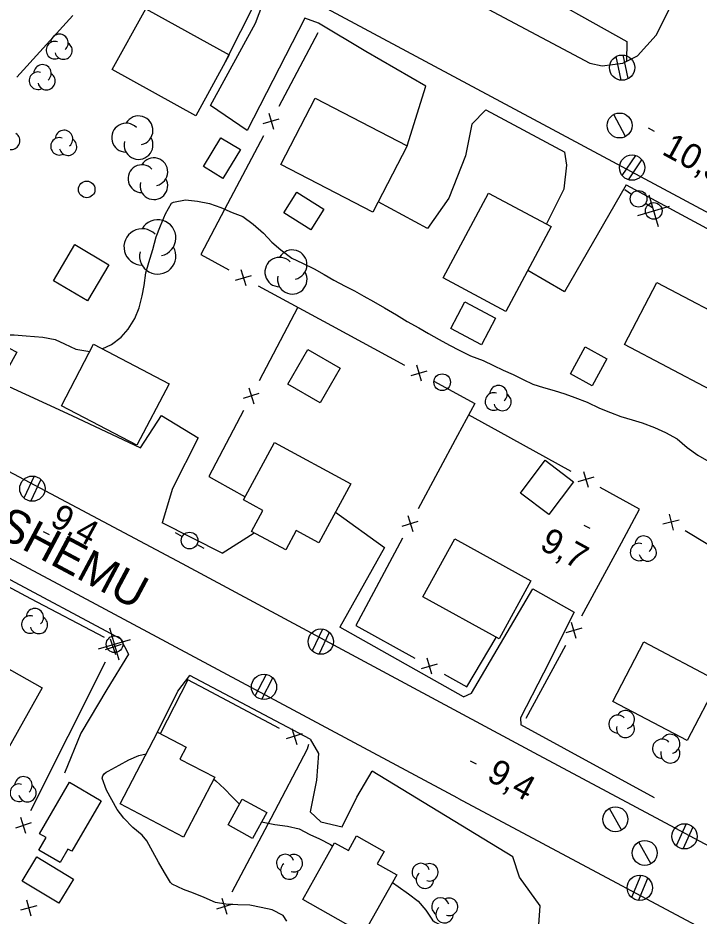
# Model space of a CAD drawing. Extents: x 219136 to 222520, y 5421589 to 5424530.
# Drawn here: x 220838.9 to 220920.8, y 5423443.6 to 5423551.5 of the extents above; entities that cross this region are included whole.
import ezdxf

# ---------------------------------------------------------------- set-up
doc = ezdxf.new("R2010")
doc.units = 0
for name, color, linetype in [('Level 1', 7, 'Continuous'), ('Level 19', 7, 'Continuous'), ('Level 21', 7, 'Continuous'), ('Level 3', 7, 'Continuous'), ('Level 31', 7, 'Continuous'), ('Level 36', 7, 'Continuous'), ('Level 37', 7, 'Continuous'), ('Level 44', 7, 'Continuous')]:
    doc.layers.add(name, color=color, linetype=linetype)

msp = doc.modelspace()

# ---------------------------------------------------------------- linework, layer by layer
at = {"layer": 'Level 1'}
for points in [[(220851.26, 5423513.13), (220852.13, 5423514.1), (220852.9, 5423515.38), (220853.43, 5423516.67), (220853.82, 5423518.08), (220854.04, 5423519.32), (220854.23, 5423520.86), (220854.62, 5423522.11), (220855.08, 5423523.67), (220855.48, 5423525.17), (220856.02, 5423526.51), (220856.59, 5423527.93), (220857.33, 5423529.22), (220857.55, 5423529.36), (220859.01, 5423529.62), (220860.45, 5423529.46), (220861.89, 5423529.19), (220863.26, 5423528.69), (220864.63, 5423528.11), (220865.9, 5423527.62), (220867.13, 5423526.71), (220868.37, 5423525.62), (220869.4, 5423524.56), (220870.47, 5423523.62), (220871.81, 5423522.64), (220873.09, 5423522.01), (220874.48, 5423521.35), (220875.68, 5423520.66), (220876.83, 5423519.96), (220878.19, 5423519.27), (220879.31, 5423518.68), (220880.46, 5423518.05), (220881.63, 5423517.43), (220882.95, 5423516.67), (220884.39, 5423515.81), (220885.67, 5423515.03), (220887.06, 5423514.24)], [(220887.06, 5423514.24), (220888.22, 5423513.58), (220889.5, 5423512.87), (220890.74, 5423512.17), (220891.91, 5423511.55), (220893.29, 5423510.9), (220894.78, 5423510.31), (220896.03, 5423509.71), (220897.2, 5423509.18), (220898.4, 5423508.66), (220899.59, 5423508.04), (220900.79, 5423507.48), (220902.04, 5423507.07), (220903.34, 5423506.71), (220904.63, 5423506.31), (220905.84, 5423505.88), (220907.3, 5423505.32), (220908.77, 5423504.62), (220910.1, 5423504.07), (220911.37, 5423503.61), (220912.7, 5423503.2), (220913.92, 5423502.83), (220915.39, 5423502.29), (220916.73, 5423501.69), (220918.11, 5423500.9), (220919.34, 5423499.86), (220920.59, 5423498.96), (220921.93, 5423498.18)], [(220834.29, 5423513.62), (220835.56, 5423513.52), (220836.93, 5423513.43), (220838.41, 5423513.4), (220839.85, 5423513.31), (220841.85, 5423513.12), (220843.33, 5423512.85), (220844.48, 5423512.34), (220845.81, 5423511.67), (220847.51, 5423511.39)], [(220849.01, 5423511.72), (220850.1, 5423512.26), (220851.26, 5423513.13)], [(220855.09, 5423451.29), (220854.36, 5423452.61), (220853.8, 5423453.3), (220852.69, 5423454.22), (220851.6, 5423455.34), (220850.8, 5423456.38), (220850.16, 5423457.55), (220849.52, 5423458.72), (220848.99, 5423460.13), (220849.06, 5423460.42), (220849.22, 5423460.66), (220849.49, 5423460.88), (220849.71, 5423461), (220851.04, 5423461.73), (220852.2, 5423462.35), (220853.41, 5423462.87), (220854.3, 5423463.07)], [(220862.4, 5423460.02), (220862.66, 5423459.82), (220863.71, 5423458.88), (220864.63, 5423457.89), (220865.5, 5423457.03)], [(220868.16, 5423454.91), (220869.77, 5423454.57), (220871.26, 5423454.37), (220872.67, 5423454.08), (220873.95, 5423453.4), (220875.12, 5423452.88), (220876.43, 5423452.19), (220876.73, 5423451.99)], [(220871.2, 5423442.98), (220870.75, 5423443.63), (220869.42, 5423444.33), (220868.11, 5423444.61), (220866.75, 5423444.89), (220865.31, 5423444.95), (220863.85, 5423445), (220862.6, 5423445.22), (220861.25, 5423445.81), (220859.98, 5423446.35), (220858.79, 5423446.78), (220857.42, 5423447.41), (220857.22, 5423447.62), (220856.48, 5423448.83), (220855.76, 5423450.07), (220855.09, 5423451.29)], [(220883.91, 5423447.61), (220884.59, 5423447.12), (220885.83, 5423446.27), (220886.97, 5423445.36), (220887.91, 5423444.3), (220888.72, 5423443.07), (220888.93, 5423442.89), (220890.08, 5423442.32), (220891.35, 5423441.7), (220892.7, 5423441.03), (220893.82, 5423440.4), (220896.12, 5423438.88)]]:
    msp.add_lwpolyline(points, dxfattribs=at)
at = {"layer": 'Level 19'}
for points in [[(220901.91, 5423560.69), (220899.43, 5423555.73), (220912.07, 5423548.65), (220912.04, 5423546.27)], [(220873.37, 5423551.45), (220866.42, 5423537.97), (220862.03, 5423540.96), (220867.41, 5423550.85), (220868.75, 5423554.39)], [(220885.67, 5423536.12), (220887.91, 5423543.29)], [(220895.11, 5423540.44), (220893.44, 5423538.72), (220892.67, 5423534.93), (220890.66, 5423529.82), (220888.12, 5423526.19), (220882.19, 5423529.4)], [(220902.41, 5423526.72), (220904.55, 5423530.96), (220904.84, 5423533.78), (220904.61, 5423535.35)], [(220912, 5423531.43), (220904.59, 5423518.59), (220900.17, 5423521.16)], [(220827.52, 5423504.09), (220833.17, 5423514.2), (220838.73, 5423511.33), (220836.68, 5423507.7), (220845.33, 5423503.71), (220853.6, 5423499.84), (220856.11, 5423503.71), (220860.52, 5423501.05), (220857.43, 5423494.94), (220856.19, 5423490.83)], [(220877.04, 5423492.09), (220882.94, 5423487.87), (220877.55, 5423478.29)], [(220863.42, 5423487.19), (220867.27, 5423489.62)], [(220892.44, 5423469.93), (220893.38, 5423470.37), (220900.76, 5423482.89), (220905.76, 5423480.09), (220902.05, 5423472.78), (220899.28, 5423467.39), (220899.33, 5423466.57)], [(220851.2, 5423476.88), (220852.17, 5423475.03), (220849.54, 5423470.79), (220846.41, 5423465.56), (220844.47, 5423460.75)], [(220855.65, 5423465.66), (220858.1, 5423470.62), (220859.55, 5423472.49)], [(220873.98, 5423464.84), (220874.99, 5423463.11), (220874.76, 5423459.91), (220874.01, 5423456.11), (220875.29, 5423454.89), (220877.84, 5423454.31), (220879.61, 5423457.88), (220881.46, 5423460.99)], [(220901.42, 5423441.42), (220901.65, 5423444.82), (220899.15, 5423448.24), (220898.35, 5423450.71)]]:
    msp.add_lwpolyline(points, dxfattribs=at)
at = {"layer": 'Level 21'}
for points in [[(220953.33, 5423511.19), (220903.15, 5423538.08), (220853.96, 5423564.44), (220851.04, 5423566.38), (220848.92, 5423568.67), (220847.29, 5423571.01), (220845.81, 5423574.35), (220845.27, 5423577.57), (220845.37, 5423580.96), (220846.22, 5423584.05), (220849.24, 5423590.53), (220872.3, 5423633.47), (220903.1, 5423691.22), (220910.99, 5423706), (220911.29, 5423707.91), (220910.56, 5423710.34), (220909.41, 5423712.18), (220908.03, 5423713.33), (220906.12, 5423714.35), (220854.72, 5423741.87), (220852.71, 5423742.23), (220850.7, 5423741.85), (220849.25, 5423740.87), (220847.05, 5423738.17)], [(220858.05, 5423572.4), (220907.64, 5423546.06), (220909.09, 5423545.73), (220911.59, 5423546.04), (220913.34, 5423546.93), (220915.58, 5423549.41), (220917.31, 5423552.83)], [(220746.34, 5423552.17), (220745.75, 5423550), (220745.8, 5423548.33), (220746.4, 5423546.69), (220747.05, 5423545.58), (220748.34, 5423544.33), (220749.89, 5423543.4), (220800.3, 5423516.91), (220858.6, 5423485.93), (220900.88, 5423463.25)], [(220887.91, 5423543.29), (220880.69, 5423547.45), (220875.01, 5423550.84), (220873.37, 5423551.45)], [(220895.11, 5423540.44), (220904.61, 5423535.35)], [(220891.76, 5423457.74), (220844.3, 5423483.15), (220786.56, 5423513.92), (220745.12, 5423535.85), (220742.9, 5423536.57), (220740.72, 5423536.46), (220738.51, 5423535.41), (220736.87, 5423533.99), (220735.87, 5423532.27), (220734.58, 5423532.43)], [(220912, 5423531.43), (220930.34, 5423521.56)], [(220863.42, 5423487.19), (220856.19, 5423490.83)], [(220851.2, 5423476.88), (220836.81, 5423484.58)], [(220892.44, 5423469.93), (220877.55, 5423478.29)], [(220873.98, 5423464.84), (220859.55, 5423472.49)], [(220915.41, 5423457.77), (220899.33, 5423466.57)], [(220900.88, 5423463.25), (220943.05, 5423440.73), (220980.92, 5423420.9), (220983.41, 5423420.36), (220985.33, 5423420.66), (220987.1, 5423421.94), (220990.34, 5423426.59)], [(220898.35, 5423450.71), (220881.46, 5423460.99)], [(220891.76, 5423457.74), (220931.7, 5423436.46), (220949.9, 5423426.94), (220976.61, 5423412.76), (220978.4, 5423410.77), (220978.96, 5423408.14), (220978.53, 5423406.33), (220978.13, 5423404.85)]]:
    msp.add_lwpolyline(points, dxfattribs=at)
at = {"layer": 'Level 3'}
for p, q in [((220914.65, 5423538.26), (220915.35, 5423537.88)), ((220906.92, 5423490.55), (220907.62, 5423490.17)), ((220841.91, 5423489.8), (220842.61, 5423489.42)), ((220893.25, 5423462.25), (220893.95, 5423461.87))]:
    msp.add_line(p, q, dxfattribs=at)
at = {"layer": 'Level 31'}
for points in [[(220854.23, 5423552.59), (220864.27, 5423547.04), (220860.24, 5423539.73), (220850.19, 5423545.28)], [(220874.59, 5423541.85), (220885.67, 5423536.12), (220881.55, 5423528.16), (220870.48, 5423533.88)], [(220865.61, 5423535.66), (220863.51, 5423532.21), (220861.16, 5423533.65), (220863.26, 5423537.09)], [(220874.08, 5423526.01), (220870.83, 5423528.05), (220872.39, 5423530.54), (220875.64, 5423528.51)], [(220890, 5423520.24), (220895.44, 5423530.44), (220902.98, 5423526.41), (220897.54, 5423516.22)], [(220849.8, 5423521.82), (220847.22, 5423517.48), (220843.13, 5423519.91), (220845.71, 5423524.25)], [(220915.69, 5423519.68), (220926.04, 5423514.26), (220922.14, 5423506.82), (220911.79, 5423512.24)], [(220894.58, 5423512.22), (220890.9, 5423514.17), (220892.6, 5423517.38), (220896.28, 5423515.42)], [(220847.97, 5423512.27), (220857.04, 5423507.51), (220853.17, 5423500.14), (220844.1, 5423504.9)], [(220877.61, 5423509.42), (220875.2, 5423505.23), (220871.3, 5423507.47), (220873.7, 5423511.66)], [(220905.29, 5423508.73), (220907.06, 5423511.95), (220909.67, 5423510.51), (220907.9, 5423507.29)], [(220869.7, 5423500.49), (220878.89, 5423495.52), (220875.05, 5423488.41), (220872.31, 5423489.89), (220871.06, 5423487.58), (220866.96, 5423489.79), (220868.32, 5423492.3), (220865.97, 5423493.58)], [(220905.68, 5423495.76), (220902.69, 5423491.82), (220899.27, 5423494.4), (220902.26, 5423498.35)], [(220891.38, 5423488.91), (220900.54, 5423483.86), (220896.71, 5423476.9), (220887.54, 5423481.95)], [(220914.12, 5423476.51), (220923.07, 5423471.82), (220919.32, 5423464.67), (220910.37, 5423469.36)], [(220841.77, 5423470.99), (220835.93, 5423460.61), (220828.53, 5423464.77), (220834.36, 5423475.15)], [(220858.77, 5423453.07), (220851.16, 5423457.05), (220855.65, 5423465.66), (220859.08, 5423463.87), (220858.33, 5423462.44), (220862.52, 5423460.25)], [(220848.88, 5423457.44), (220845.35, 5423451.36), (220844.88, 5423451.63), (220843.95, 5423450.02), (220841.38, 5423451.51), (220842.24, 5423453.01), (220841.47, 5423453.46), (220845.06, 5423459.65)], [(220864.13, 5423454.54), (220865.83, 5423457.63), (220868.77, 5423456.01), (220867.07, 5423452.92)], [(220880.43, 5423441.43), (220873.1, 5423445.56), (220876.94, 5423452.37), (220878.59, 5423451.45), (220879.59, 5423453.22), (220882.91, 5423451.35), (220882.07, 5423449.87), (220884.43, 5423448.54)], [(220841.12, 5423450.69), (220845.54, 5423448.03), (220843.79, 5423445.13), (220839.37, 5423447.79)]]:
    msp.add_lwpolyline(points, close=True, dxfattribs=at)
at = {"layer": 'Level 36'}
for p, q in [((220910.76, 5423546.84), (220911.35, 5423544)), ((220912.24, 5423544.2), (220911.65, 5423547.04)), ((220911.91, 5423537.22), (220910.51, 5423539.88)), ((220913.11, 5423534.95), (220911.49, 5423532.55)), ((220912.27, 5423532.05), (220913.89, 5423534.45)), ((220911.82, 5423530.86), (220912.65, 5423530.31)), ((220915.87, 5423526.38), (220914.74, 5423530.21)), ((220913.39, 5423527.73), (220917.22, 5423528.86)), ((220915.16, 5423528.66), (220914.32, 5423529.2)), ((220840.8, 5423496.43), (220839.58, 5423493.8)), ((220840.42, 5423493.43), (220841.64, 5423496.06)), ((220857.75, 5423489.67), (220858.62, 5423489.19)), ((220861.25, 5423487.74), (220860.37, 5423488.21)), ((220851.05, 5423474.32), (220849.92, 5423478.15)), ((220875.5, 5423478.05), (220874.24, 5423475.43)), ((220875.08, 5423475.05), (220876.34, 5423477.67)), ((220848.57, 5423475.67), (220852.4, 5423476.8)), ((220868.69, 5423472.6), (220867.36, 5423470.02)), ((220868.19, 5423469.62), (220869.52, 5423472.2)), ((220909.96, 5423456.53), (220911.42, 5423453.91)), ((220919.21, 5423454.66), (220917.99, 5423452.03)), ((220918.83, 5423451.66), (220920.05, 5423454.29)), ((220913.48, 5423452.49), (220914.94, 5423449.87)), ((220913.75, 5423448.49), (220912.63, 5423445.81)), ((220913.49, 5423445.47), (220914.61, 5423448.15))]:
    msp.add_line(p, q, dxfattribs=at)
for centre, radius in [((220911.5, 5423545.51), 1.52), ((220911.2, 5423538.56), 1.5), ((220912.7, 5423533.5), 1.52), ((220847.13, 5423530.88), 1), ((220913.49, 5423529.75), 1), ((220915.31, 5423528.3), 1), ((220889.87, 5423507.72), 1), ((220840.6, 5423494.93), 1.52), ((220859.5, 5423488.7), 1), ((220850.49, 5423476.24), 1), ((220875.28, 5423476.55), 1.52), ((220868.45, 5423471.11), 1.52), ((220910.7, 5423455.21), 1.5), ((220919.01, 5423453.16), 1.52), ((220914.22, 5423451.17), 1.5), ((220913.63, 5423446.98), 1.52)]:
    msp.add_circle(centre, radius, dxfattribs=at)
at = {"layer": 'Level 37'}
for p, q in [((220869.02, 5423540.04), (220869.61, 5423538.13)), ((220868.36, 5423538.79), (220870.27, 5423539.38)), ((220865.04, 5423519.97), (220866.96, 5423520.54)), ((220866.29, 5423519.3), (220865.72, 5423521.22)), ((220887.38, 5423507.85), (220886.81, 5423509.77)), ((220886.13, 5423508.52), (220888.05, 5423509.09)), ((220865.97, 5423505.8), (220867.88, 5423506.4)), ((220866.63, 5423507.06), (220867.22, 5423505.14)), ((220906.85, 5423497.01), (220907.41, 5423495.09)), ((220908.09, 5423496.33), (220906.17, 5423495.77)), ((220885.75, 5423491.69), (220886.33, 5423489.77)), ((220918.36, 5423491.15), (220916.41, 5423490.67)), ((220917.15, 5423491.88), (220917.63, 5423489.94)), ((220885.08, 5423490.44), (220887, 5423491.02)), ((220906.65, 5423478.17), (220904.73, 5423477.6)), ((220905.98, 5423476.93), (220905.41, 5423478.85)), ((220851.26, 5423476.21), (220849.36, 5423475.58)), ((220850.62, 5423474.95), (220849.99, 5423476.85)), ((220887.39, 5423473.33), (220889.31, 5423473.89)), ((220888.63, 5423472.65), (220888.07, 5423474.57)), ((220873.04, 5423465.46), (220871.13, 5423464.87)), ((220871.79, 5423466.12), (220872.38, 5423464.21)), ((220840.47, 5423454.77), (220838.57, 5423454.15)), ((220839.83, 5423453.51), (220839.21, 5423455.41)), ((220841.13, 5423444.82), (220839.19, 5423444.31)), ((220839.9, 5423445.53), (220840.41, 5423443.6)), ((220864.67, 5423445.02), (220862.75, 5423444.42)), ((220864.01, 5423443.76), (220863.41, 5423445.68))]:
    msp.add_line(p, q, dxfattribs=at)
for points in [[(220867.47, 5423553.51), (220863.78, 5423546.2)], [(220838.74, 5423544.37), (220845.46, 5423551.78)], [(220874.93, 5423549.69), (220870.25, 5423540.85)], [(220868.38, 5423537.32), (220863.71, 5423528.48)], [(220863.71, 5423528.48), (220860.84, 5423523.06), (220864.24, 5423521.21)], [(220867.76, 5423519.3), (220876.55, 5423514.53)], [(220872.51, 5423516.72), (220867.85, 5423507.87)], [(220876.55, 5423514.53), (220885.34, 5423509.76)], [(220888.85, 5423507.86), (220893.78, 5423505.18), (220891.71, 5423501.31)], [(220865.99, 5423504.33), (220861.82, 5423496.4), (220862.73, 5423495.89)], [(220896.62, 5423501.83), (220893.04, 5423503.8)], [(220891.71, 5423501.31), (220886.99, 5423492.49)], [(220905.38, 5423497.01), (220896.62, 5423501.83)], [(220862.73, 5423495.89), (220866.17, 5423493.96)], [(220911.42, 5423488.44), (220913.61, 5423492.48), (220908.88, 5423495.08)], [(220885.1, 5423488.97), (220880.38, 5423480.15)], [(220927.65, 5423484.69), (220919.1, 5423489.87)], [(220906.65, 5423479.65), (220911.42, 5423488.44)], [(220840.4, 5423481.7), (220836.39, 5423483.8), (220833.91, 5423478.92)], [(220849.26, 5423477.06), (220840.4, 5423481.7)], [(220880.38, 5423480.15), (220879.49, 5423478.49), (220886.6, 5423474.57)], [(220890.1, 5423472.64), (220892.83, 5423471.14), (220896.37, 5423477.05)], [(220896.37, 5423477.05), (220896.39, 5423477.08)], [(220899.97, 5423467.34), (220904.74, 5423476.13)], [(220844.91, 5423465.18), (220849.41, 5423474.11)], [(220861.48, 5423470.79), (220859.3, 5423471.95), (220855.98, 5423465.48)], [(220870.32, 5423466.1), (220861.48, 5423470.79)], [(220840.42, 5423456.25), (220844.91, 5423465.18)], [(220869.3, 5423455.34), (220873.69, 5423463.68), (220873.85, 5423464.23)], [(220864.64, 5423446.49), (220869.3, 5423455.34)]]:
    msp.add_lwpolyline(points, dxfattribs=at)
at = {"layer": 'Level 44'}
for centre, radius, start, end in [((220843.86, 5423548.49), 1.05, 309.6881, 177.1452), ((220843.3, 5423547.61), 1.05, 71.5343, 297.2229), ((220844.34, 5423547.56), 1.05, 194.3558, 57.0401), ((220841.82, 5423544.82), 1.05, 309.6881, 177.1452), ((220841.26, 5423543.94), 1.05, 71.5343, 297.2229), ((220842.3, 5423543.89), 1.05, 194.3558, 57.0401), ((220853.36, 5423537.97), 1.74, 282.2692, 149.7262), ((220851.87, 5423537.1), 1.74, 44.1153, 269.8039), ((220838.05, 5423536.72), 1.05, 194.3558, 57.0401), ((220844.41, 5423536.94), 1.05, 309.6881, 177.1452), ((220843.85, 5423536.06), 1.05, 71.5343, 297.2229), ((220844.89, 5423536.01), 1.05, 194.3558, 57.0401), ((220853.36, 5423536.23), 1.74, 166.9368, 29.6212), ((220855.21, 5423533), 1.67, 282.2692, 149.7262), ((220853.77, 5423532.17), 1.67, 44.1153, 269.8039), ((220855.21, 5423531.34), 1.67, 166.9368, 29.6212), ((220855.67, 5423525.06), 2.18, 282.2692, 149.7262), ((220853.79, 5423523.97), 2.18, 44.1153, 269.8039), ((220855.67, 5423522.88), 2.18, 166.9368, 29.6212), ((220871.85, 5423521.84), 1.77, 282.2692, 149.7262), ((220870.33, 5423520.95), 1.77, 44.1153, 269.8039), ((220871.85, 5423520.07), 1.77, 166.9368, 29.6212), ((220896.64, 5423506.28), 1.05, 309.6881, 177.1452), ((220896.08, 5423505.4), 1.05, 71.5343, 297.2229), ((220897.12, 5423505.35), 1.05, 194.3558, 57.0401), ((220914.1, 5423488.2), 1.05, 309.6881, 177.1452), ((220913.54, 5423487.32), 1.05, 71.5343, 297.2229), ((220914.58, 5423487.27), 1.05, 194.3558, 57.0401), ((220840.9, 5423479.49), 1.05, 309.6881, 177.1452), ((220840.34, 5423478.61), 1.05, 71.5343, 297.2229), ((220841.38, 5423478.56), 1.05, 194.3558, 57.0401), ((220910.98, 5423466.65), 1.08, 44.1153, 269.8039), ((220911.91, 5423467.19), 1.08, 282.2692, 149.7262), ((220911.91, 5423466.11), 1.08, 166.9368, 29.6212), ((220917.3, 5423464.27), 1.15, 282.2692, 149.7262), ((220916.31, 5423463.69), 1.15, 44.1153, 269.8039), ((220917.3, 5423463.11), 1.15, 166.9368, 29.6212), ((220839.53, 5423459.28), 1.05, 309.6881, 177.1452), ((220838.97, 5423458.4), 1.05, 71.5343, 297.2229), ((220840.01, 5423458.35), 1.05, 194.3558, 57.0401), ((220871, 5423449.96), 1.05, 15.4747, 238.159), ((220872.04, 5423449.93), 1.05, 252.6532, 118.3418), ((220871.5, 5423449.05), 1.05, 130.807, 358.2641), ((220887.3, 5423448.87), 1.05, 15.4747, 238.159), ((220888.34, 5423448.84), 1.05, 252.6532, 118.3418), ((220887.8, 5423447.96), 1.05, 130.807, 358.2641), ((220889.66, 5423444.72), 1.05, 15.4747, 238.159), ((220890.7, 5423444.69), 1.05, 252.6532, 118.3418), ((220890.16, 5423443.81), 1.05, 130.807, 358.2641)]:
    msp.add_arc(centre, radius, start, end, dxfattribs=at)

# ---------------------------------------------------------------- texts
at = {"layer": 'Level 21'}
msp.add_text('KAUATSHEMU', height=4, rotation=331.9466, dxfattribs=at).set_placement((220820.28, 5423497.82))
at = {"layer": 'Level 3'}
for s, p in [('10,3', (220916.15, 5423535.18)), ('9,4', (220842.57, 5423490.63)), ('9,7', (220901.44, 5423487.76)), ('9,4', (220895.08, 5423459.99))]:
    msp.add_text(s, height=3, rotation=331.383, dxfattribs=at).set_placement(p)

doc.saveas('drawing.dxf')
